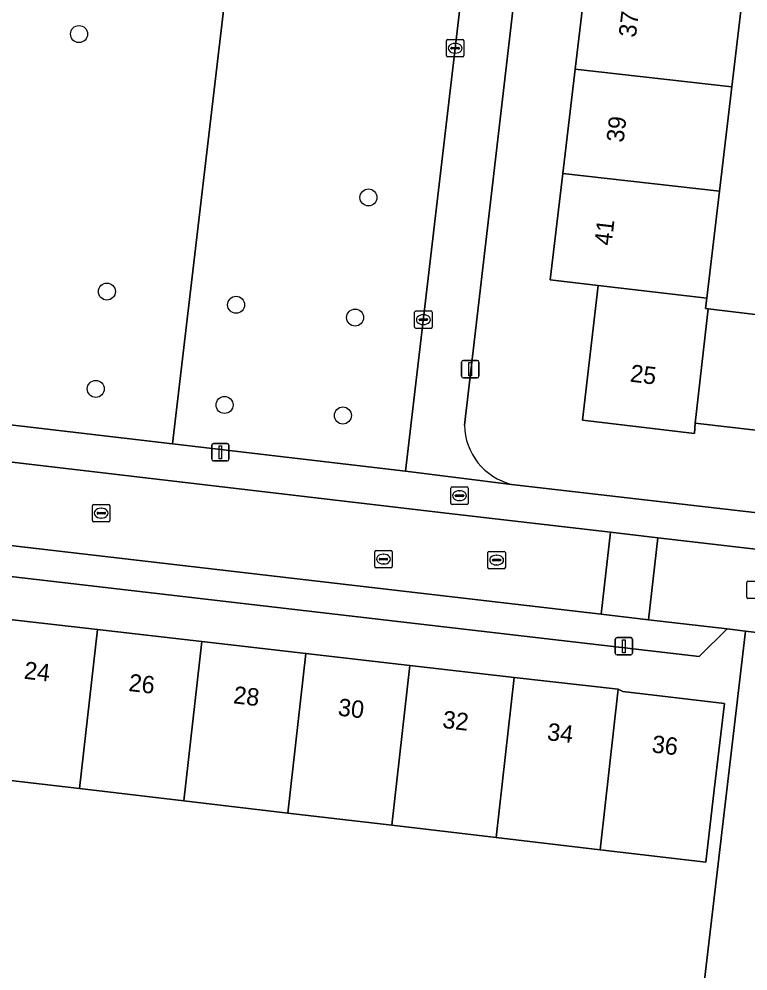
# Model space of a CAD drawing. Extents: x 161241 to 161758, y 384138 to 384885.
# Drawn here: x 161418.6 to 161460.5, y 384397.6 to 384452.3 of the extents above; entities that cross this region are included whole.
import ezdxf

# ---------------------------------------------------------------- set-up
doc = ezdxf.new("R2010")
doc.units = 0
for name, color, linetype in [('IMGEO_Boom', 7, 'Continuous'), ('IMGEO_Brandkraan', 7, 'Continuous'), ('IMGEO_Erf', 7, 'Continuous'), ('IMGEO_Groenvoorziening', 7, 'Continuous'), ('IMGEO_Kolk', 7, 'Continuous'), ('IMGEO_Lichtmast', 7, 'Continuous'), ('IMGEO_Pand', 7, 'Continuous'), ('IMGEO_Pand_nummerreeks', 7, 'Continuous'), ('IMGEO_Parkeervlak_open', 7, 'Continuous'), ('IMGEO_Rijbaan_lokaal_open', 7, 'Continuous'), ('IMGEO_Rioolput', 7, 'Continuous'), ('IMGEO_Voetpad_open', 7, 'Continuous')]:
    doc.layers.add(name, color=color, linetype=linetype)

msp = doc.modelspace()

# ---------------------------------------------------------------- linework, layer by layer
at = {"layer": 'IMGEO_Boom'}
for centre in [(161422.071, 384451.466), (161438.718, 384442.073), (161423.675, 384436.66), (161431.104, 384435.903), (161437.946, 384435.168), (161423.034, 384431.071), (161430.439, 384430.143), (161437.247, 384429.539)]:
    msp.add_circle(centre, 0.489, dxfattribs=at)
at = {"layer": 'IMGEO_Brandkraan'}
for p, q in [((161443.452, 384424.504), (161443.452, 384425.356)), ((161443.527, 384425.43), (161444.379, 384425.43)), ((161444.453, 384425.356), (161444.453, 384424.504)), ((161443.711, 384424.924), (161443.711, 384424.936)), ((161444.149, 384424.887), (161443.751, 384424.887)), ((161443.754, 384424.973), (161444.152, 384424.973)), ((161443.94, 384425.21), (161443.965, 384425.21)), ((161444.195, 384424.936), (161444.195, 384424.924)), ((161444.379, 384424.43), (161443.527, 384424.43)), ((161443.963, 384424.65), (161443.938, 384424.65))]:
    msp.add_line(p, q, dxfattribs=at)
for points in [[(161443.452, 384424.504), (161443.452, 384425.356)], [(161443.527, 384425.43), (161444.379, 384425.43)], [(161444.453, 384425.356), (161444.453, 384424.504)], [(161444.379, 384424.43), (161443.527, 384424.43)]]:
    msp.add_lwpolyline(points, dxfattribs=at)
for centre, radius, start, end in [((161443.529, 384425.354), 0.0765, 91.552, 178.448), ((161443.529, 384425.354), 0.0765, 91.552, 178.448), ((161444.377, 384425.354), 0.0765, 1.552, 88.448), ((161444.377, 384425.354), 0.0765, 1.552, 88.448), ((161443.751, 384424.933), 0.0403, 85.8775, 175.7526), ((161443.748, 384424.923), 0.0366, 178.938, 274.7102), ((161444.152, 384424.93), 0.043, 264.8664, 352.4533), ((161444.156, 384424.935), 0.0386, 1.7309, 96.639), ((161443.529, 384424.506), 0.0765, 181.552, 268.448), ((161443.529, 384424.506), 0.0765, 181.552, 268.448), ((161444.377, 384424.506), 0.0765, 271.552, 358.448), ((161444.377, 384424.506), 0.0765, 271.552, 358.448)]:
    msp.add_arc(centre, radius, start, end, dxfattribs=at)
for centre, major_axis, ratio, start_param, end_param in [((161443.939, 384424.93), (-0.387, 0.002), 0.722429, 4.712389, 7.853982), ((161443.964, 384424.93), (-0.39, 0.002), 0.717154, 1.570796, 4.712389)]:
    msp.add_ellipse(centre, major_axis=major_axis, ratio=ratio, start_param=start_param, end_param=end_param, dxfattribs=at)
at = {"layer": 'IMGEO_Erf'}
for points in [[(161451.223, 384488.839), (161444.232, 384428.985)], [(161505.583, 384423.539), (161496.808, 384424.548), (161496.597, 384422.814), (161488.87, 384423.713), (161484.22, 384424.254), (161484.829, 384429.232), (161481.869, 384429.57), (161479.043, 384429.893), (161478.461, 384424.915), (161473.71, 384425.475), (161466.1, 384426.371), (161466.285, 384428.091), (161457.502, 384429.091), (161457.458, 384428.498), (161451.03, 384429.277), (161451.926, 384437.019), (161449.164, 384437.343), (161449.889, 384443.443), (161450.602, 384449.443), (161451.289, 384455.23)], [(161460.318, 384454.435), (161459.607, 384448.436), (161458.896, 384442.435), (161458.166, 384436.284), (161458.095, 384435.682), (161458.25, 384435.664), (161466.874, 384434.642), (161466.982, 384435.546), (161474.774, 384434.622), (161479.257, 384434.091), (161479.533, 384436.415), (161482.623, 384436.049), (161485.551, 384435.702), (161485.276, 384433.379), (161489.93, 384432.827), (161497.551, 384431.924), (161497.509, 384431.003), (161506.232, 384429.97)], [(161446.947, 384425.581), (161500, 384419.47), (161517.124, 384417.504)], [(161415.847, 384394.67), (161424.15, 384393.701), (161423.913, 384391.799), (161426.306, 384391.565), (161428.717, 384391.33), (161428.41, 384388.19), (161456.596, 384384.852), (161460.391, 384417.148), (161459.347, 384417.271), (161457.727, 384415.687), (161417.974, 384420.297)], [(161417.063, 384417.929), (161423.139, 384417.232), (161429.127, 384416.546), (161435.115, 384415.86), (161441.102, 384415.173), (161447.09, 384414.487), (161453.078, 384413.8), (161453.34, 384413.677), (161459.187, 384412.985), (161458.605, 384408.02), (161458.118, 384403.868), (161452.038, 384404.582), (161446.052, 384405.284), (161440.066, 384405.987), (161434.08, 384406.689), (161428.094, 384407.392), (161422.108, 384408.094), (161415.958, 384408.816)]]:
    msp.add_lwpolyline(points, dxfattribs=at)
msp.add_arc((161447.821, 384429.063), 3.589, 181.2373, 255.9138, dxfattribs=at)
at = {"layer": 'IMGEO_Groenvoorziening'}
msp.add_lwpolyline([(161409.377, 384462.778), (161397.9, 384454.084), (161411.738, 384445.455), (161410.62, 384434.912), (161410.092, 384429.939), (161427.439, 384427.904), (161432.833, 384473.658)], dxfattribs=at)
msp.add_lwpolyline([(161445.975, 384470.082), (161446.228, 384472.086), (161432.833, 384473.658), (161427.439, 384427.904), (161440.852, 384426.331)], close=True, dxfattribs=at)
at = {"layer": 'IMGEO_Kolk'}
for p, q in [((161443.2, 384450.222), (161443.2, 384451.074)), ((161443.275, 384451.148), (161444.127, 384451.148)), ((161444.201, 384451.074), (161444.201, 384450.222)), ((161443.459, 384450.642), (161443.459, 384450.654)), ((161443.897, 384450.605), (161443.499, 384450.605)), ((161443.502, 384450.691), (161443.9, 384450.691)), ((161443.688, 384450.928), (161443.713, 384450.928)), ((161443.943, 384450.654), (161443.943, 384450.642)), ((161444.127, 384450.148), (161443.275, 384450.148)), ((161443.711, 384450.368), (161443.686, 384450.368)), ((161441.373, 384434.622), (161441.373, 384435.474)), ((161441.448, 384435.548), (161442.3, 384435.548)), ((161441.861, 384435.328), (161441.886, 384435.328)), ((161442.374, 384435.474), (161442.374, 384434.622)), ((161441.632, 384435.042), (161441.632, 384435.054)), ((161442.07, 384435.005), (161441.672, 384435.005)), ((161441.675, 384435.091), (161442.073, 384435.091)), ((161441.884, 384434.768), (161441.859, 384434.768)), ((161442.116, 384435.054), (161442.116, 384435.042)), ((161442.3, 384434.548), (161441.448, 384434.548)), ((161422.848, 384423.5), (161422.848, 384424.352)), ((161422.923, 384424.426), (161423.775, 384424.426)), ((161423.336, 384424.206), (161423.361, 384424.206)), ((161423.849, 384424.352), (161423.849, 384423.5)), ((161423.107, 384423.92), (161423.107, 384423.932)), ((161423.545, 384423.883), (161423.147, 384423.883)), ((161423.15, 384423.969), (161423.548, 384423.969)), ((161423.359, 384423.646), (161423.334, 384423.646)), ((161423.591, 384423.932), (161423.591, 384423.92)), ((161423.775, 384423.426), (161422.923, 384423.426)), ((161445.587, 384420.803), (161445.587, 384421.655)), ((161445.662, 384421.729), (161446.514, 384421.729)), ((161446.075, 384421.509), (161446.1, 384421.509)), ((161446.588, 384421.655), (161446.588, 384420.803)), ((161445.846, 384421.223), (161445.846, 384421.235)), ((161446.284, 384421.186), (161445.886, 384421.186)), ((161445.889, 384421.272), (161446.287, 384421.272)), ((161446.098, 384420.949), (161446.073, 384420.949)), ((161446.33, 384421.235), (161446.33, 384421.223)), ((161446.514, 384420.729), (161445.662, 384420.729)), ((161460.466, 384419.094), (161460.466, 384419.946)), ((161460.541, 384420.02), (161461.393, 384420.02)), ((161461.393, 384419.02), (161460.541, 384419.02))]:
    msp.add_line(p, q, dxfattribs=at)
for points in [[(161443.2, 384450.222), (161443.2, 384451.074)], [(161443.275, 384451.148), (161444.127, 384451.148)], [(161444.201, 384451.074), (161444.201, 384450.222)], [(161444.127, 384450.148), (161443.275, 384450.148)], [(161441.373, 384434.622), (161441.373, 384435.474)], [(161441.448, 384435.548), (161442.3, 384435.548)], [(161442.374, 384435.474), (161442.374, 384434.622)], [(161442.3, 384434.548), (161441.448, 384434.548)], [(161422.848, 384423.5), (161422.848, 384424.352)], [(161422.923, 384424.426), (161423.775, 384424.426)], [(161423.849, 384424.352), (161423.849, 384423.5)], [(161423.775, 384423.426), (161422.923, 384423.426)], [(161445.587, 384420.803), (161445.587, 384421.655)], [(161445.662, 384421.729), (161446.514, 384421.729)], [(161446.588, 384421.655), (161446.588, 384420.803)], [(161446.514, 384420.729), (161445.662, 384420.729)], [(161460.466, 384419.094), (161460.466, 384419.946)], [(161460.541, 384420.02), (161461.393, 384420.02)], [(161461.393, 384419.02), (161460.541, 384419.02)]]:
    msp.add_lwpolyline(points, dxfattribs=at)
for centre, radius, start, end in [((161443.277, 384451.072), 0.0765, 91.552, 178.448), ((161443.277, 384451.072), 0.0765, 91.552, 178.448), ((161444.125, 384451.072), 0.0765, 1.552, 88.448), ((161444.125, 384451.072), 0.0765, 1.552, 88.448), ((161443.499, 384450.651), 0.0403, 85.8775, 175.7526), ((161443.496, 384450.641), 0.0366, 178.938, 274.7102), ((161443.9, 384450.648), 0.043, 264.8664, 352.4533), ((161443.904, 384450.653), 0.0386, 1.7309, 96.639), ((161443.277, 384450.224), 0.0765, 181.552, 268.448), ((161443.277, 384450.224), 0.0765, 181.552, 268.448), ((161444.125, 384450.224), 0.0765, 271.552, 358.448), ((161444.125, 384450.224), 0.0765, 271.552, 358.448), ((161441.45, 384435.472), 0.0765, 91.552, 178.448), ((161441.45, 384435.472), 0.0765, 91.552, 178.448), ((161442.298, 384435.472), 0.0765, 1.552, 88.448), ((161442.298, 384435.472), 0.0765, 1.552, 88.448), ((161441.45, 384434.624), 0.0765, 181.552, 268.448), ((161441.45, 384434.624), 0.0765, 181.552, 268.448), ((161441.672, 384435.051), 0.0403, 85.8775, 175.7526), ((161441.669, 384435.041), 0.0366, 178.938, 274.7102), ((161442.073, 384435.048), 0.043, 264.8664, 352.4533), ((161442.077, 384435.053), 0.0386, 1.7309, 96.639), ((161442.298, 384434.624), 0.0765, 271.552, 358.448), ((161442.298, 384434.624), 0.0765, 271.552, 358.448), ((161422.925, 384424.35), 0.0765, 91.552, 178.448), ((161422.925, 384424.35), 0.0765, 91.552, 178.448), ((161423.773, 384424.35), 0.0765, 1.552, 88.448), ((161423.773, 384424.35), 0.0765, 1.552, 88.448), ((161423.147, 384423.929), 0.0403, 85.8775, 175.7526), ((161423.144, 384423.919), 0.0366, 178.938, 274.7102), ((161423.548, 384423.926), 0.043, 264.8664, 352.4533), ((161423.552, 384423.931), 0.0386, 1.7309, 96.639), ((161422.925, 384423.502), 0.0765, 181.552, 268.448), ((161422.925, 384423.502), 0.0765, 181.552, 268.448), ((161423.773, 384423.502), 0.0765, 271.552, 358.448), ((161423.773, 384423.502), 0.0765, 271.552, 358.448), ((161445.664, 384421.653), 0.0765, 91.552, 178.448), ((161445.664, 384421.653), 0.0765, 91.552, 178.448), ((161446.512, 384421.653), 0.0765, 1.552, 88.448), ((161446.512, 384421.653), 0.0765, 1.552, 88.448), ((161445.886, 384421.232), 0.0403, 85.8775, 175.7526), ((161445.883, 384421.222), 0.0366, 178.938, 274.7102), ((161446.287, 384421.229), 0.043, 264.8664, 352.4533), ((161446.291, 384421.234), 0.0386, 1.7309, 96.639), ((161445.664, 384420.805), 0.0765, 181.552, 268.448), ((161445.664, 384420.805), 0.0765, 181.552, 268.448), ((161446.512, 384420.805), 0.0765, 271.552, 358.448), ((161446.512, 384420.805), 0.0765, 271.552, 358.448), ((161460.543, 384419.944), 0.0765, 91.552, 178.448), ((161460.543, 384419.944), 0.0765, 91.552, 178.448), ((161460.543, 384419.096), 0.0765, 181.552, 268.448), ((161460.543, 384419.096), 0.0765, 181.552, 268.448)]:
    msp.add_arc(centre, radius, start, end, dxfattribs=at)
for centre, major_axis, ratio, start_param, end_param in [((161443.687, 384450.648), (-0.387, 0.002), 0.722429, 4.712389, 7.853982), ((161443.712, 384450.648), (-0.39, 0.002), 0.717154, 1.570796, 4.712389), ((161441.86, 384435.048), (-0.387, 0.002), 0.722429, 4.712389, 7.853982), ((161441.885, 384435.048), (-0.39, 0.002), 0.717154, 1.570796, 4.712389), ((161423.335, 384423.926), (-0.387, 0.002), 0.722429, 4.712389, 7.853982), ((161423.36, 384423.926), (-0.39, 0.002), 0.717154, 1.570796, 4.712389), ((161446.074, 384421.229), (-0.387, 0.002), 0.722429, 4.712389, 7.853982), ((161446.099, 384421.229), (-0.39, 0.002), 0.717154, 1.570796, 4.712389)]:
    msp.add_ellipse(centre, major_axis=major_axis, ratio=ratio, start_param=start_param, end_param=end_param, dxfattribs=at)
at = {"layer": 'IMGEO_Lichtmast'}
for p, q in [((161444.075, 384431.801), (161444.075, 384432.601)), ((161444.075, 384432.601), (161444.075, 384431.801)), ((161444.175, 384432.701), (161444.965, 384432.701)), ((161444.965, 384432.701), (161444.175, 384432.701)), ((161445.065, 384432.601), (161445.065, 384431.801)), ((161445.065, 384431.801), (161445.065, 384432.601)), ((161444.965, 384431.701), (161444.175, 384431.701)), ((161444.175, 384431.701), (161444.965, 384431.701)), ((161429.704, 384427.026), (161429.704, 384427.826)), ((161429.704, 384427.826), (161429.704, 384427.026)), ((161429.804, 384427.926), (161430.594, 384427.926)), ((161430.594, 384427.926), (161429.804, 384427.926)), ((161430.694, 384427.826), (161430.694, 384427.026)), ((161430.694, 384427.026), (161430.694, 384427.826)), ((161430.594, 384426.926), (161429.804, 384426.926)), ((161429.804, 384426.926), (161430.594, 384426.926)), ((161452.91, 384415.874), (161452.91, 384416.674)), ((161452.91, 384416.674), (161452.91, 384415.874)), ((161453.01, 384416.774), (161453.8, 384416.774)), ((161453.8, 384416.774), (161453.01, 384416.774)), ((161453.9, 384416.674), (161453.9, 384415.874)), ((161453.9, 384415.874), (161453.9, 384416.674)), ((161453.8, 384415.774), (161453.01, 384415.774)), ((161453.01, 384415.774), (161453.8, 384415.774))]:
    msp.add_line(p, q, dxfattribs=at)
for points in [[(161444.495, 384432.576), (161444.645, 384432.576), (161444.645, 384431.826), (161444.495, 384431.826), (161444.495, 384432.576)], [(161430.124, 384427.801), (161430.274, 384427.801), (161430.274, 384427.051), (161430.124, 384427.051), (161430.124, 384427.801)], [(161453.33, 384416.649), (161453.48, 384416.649), (161453.48, 384415.899), (161453.33, 384415.899), (161453.33, 384416.649)]]:
    msp.add_lwpolyline(points, dxfattribs=at)
for centre, start, end in [((161444.175, 384432.601), 90, 180), ((161444.175, 384432.601), 90, 180), ((161444.965, 384432.601), 0, 90), ((161444.965, 384432.601), 360, 90), ((161444.175, 384431.801), 180, 270), ((161444.175, 384431.801), 180, 270), ((161444.965, 384431.801), 270, 0), ((161444.965, 384431.801), 270, 0), ((161429.804, 384427.826), 90, 180), ((161429.804, 384427.826), 90, 180), ((161430.594, 384427.826), 0, 90), ((161430.594, 384427.826), 360, 90), ((161429.804, 384427.026), 180, 270), ((161429.804, 384427.026), 180, 270), ((161430.594, 384427.026), 270, 0), ((161430.594, 384427.026), 270, 0), ((161453.01, 384416.674), 90, 180), ((161453.01, 384416.674), 90, 180), ((161453.8, 384416.674), 0, 90), ((161453.8, 384416.674), 360, 90), ((161453.01, 384415.874), 180, 270), ((161453.01, 384415.874), 180, 270), ((161453.8, 384415.874), 270, 0), ((161453.8, 384415.874), 270, 0)]:
    msp.add_arc(centre, 0.1, start, end, dxfattribs=at)
at = {"layer": 'IMGEO_Pand'}
for points in [[(161451.061, 384455.472), (161451.038, 384455.281), (161451.289, 384455.23), (161450.602, 384449.443), (161459.607, 384448.436), (161460.318, 384454.435)], [(161458.896, 384442.435), (161459.607, 384448.436), (161450.602, 384449.443), (161449.889, 384443.443)], [(161449.889, 384443.443), (161449.164, 384437.343), (161451.926, 384437.019), (161458.166, 384436.284), (161458.896, 384442.435)], [(161458.25, 384435.664), (161458.095, 384435.682), (161458.166, 384436.284), (161451.926, 384437.019), (161451.03, 384429.277), (161457.458, 384428.498), (161457.502, 384429.091)], [(161458.25, 384435.664), (161457.502, 384429.091), (161466.285, 384428.091), (161466.874, 384434.642)], [(161416.056, 384409.721), (161415.958, 384408.816), (161422.108, 384408.094), (161423.139, 384417.232), (161417.063, 384417.929), (161416.852, 384416.18)], [(161429.127, 384416.546), (161423.139, 384417.232), (161422.108, 384408.094), (161428.094, 384407.392)], [(161428.094, 384407.392), (161434.08, 384406.689), (161435.115, 384415.86), (161429.127, 384416.546)], [(161434.08, 384406.689), (161440.066, 384405.987), (161441.102, 384415.173), (161435.115, 384415.86)], [(161447.09, 384414.487), (161441.102, 384415.173), (161440.066, 384405.987), (161446.052, 384405.284)], [(161446.052, 384405.284), (161452.038, 384404.582), (161453.078, 384413.8), (161447.09, 384414.487)], [(161452.038, 384404.582), (161458.118, 384403.868), (161458.605, 384408.02), (161459.187, 384412.985), (161453.34, 384413.677), (161453.078, 384413.8)]]:
    msp.add_lwpolyline(points, close=True, dxfattribs=at)
at = {"layer": 'IMGEO_Parkeervlak_open'}
msp.add_lwpolyline([(161417.282, 384422.167), (161417.974, 384420.297), (161457.727, 384415.687), (161459.347, 384417.271), (161454.814, 384417.799), (161452.092, 384418.115)], close=True, dxfattribs=at)
at = {"layer": 'IMGEO_Rijbaan_lokaal_open'}
for points in [[(161417.282, 384422.167), (161452.092, 384418.115), (161452.639, 384422.825), (161443.686, 384423.864), (161404.653, 384428.447), (161404.094, 384423.73)], [(161454.814, 384417.799), (161455.361, 384422.51), (161452.639, 384422.825), (161452.092, 384418.115)]]:
    msp.add_lwpolyline(points, close=True, dxfattribs=at)
for points in [[(161516.896, 384415.376), (161500, 384417.331), (161455.361, 384422.51), (161454.814, 384417.799), (161459.347, 384417.271), (161460.391, 384417.148), (161464.436, 384416.673), (161465.637, 384416.532), (161489.559, 384413.756), (161500, 384412.531), (161510.318, 384411.321), (161514.204, 384410.875), (161523.243, 384409.923)], [(161506.638, 384379.095), (161463.961, 384384), (161461.689, 384384.202), (161461.694, 384384.264), (161460.643, 384384.386), (161464.436, 384416.673), (161460.391, 384417.148), (161456.596, 384384.852), (161428.41, 384388.19), (161425.953, 384388.43), (161423.606, 384388.659), (161423.913, 384391.799), (161424.15, 384393.701), (161415.847, 384394.67)]]:
    msp.add_lwpolyline(points, dxfattribs=at)
at = {"layer": 'IMGEO_Rioolput'}
for p, q in [((161439.077, 384420.858), (161439.077, 384421.71)), ((161439.152, 384421.784), (161440.004, 384421.784)), ((161439.565, 384421.564), (161439.59, 384421.564)), ((161440.078, 384421.71), (161440.078, 384420.858)), ((161439.336, 384421.278), (161439.336, 384421.29)), ((161439.774, 384421.241), (161439.376, 384421.241)), ((161439.379, 384421.327), (161439.777, 384421.327)), ((161439.588, 384421.004), (161439.563, 384421.004)), ((161439.82, 384421.29), (161439.82, 384421.278)), ((161440.004, 384420.784), (161439.152, 384420.784))]:
    msp.add_line(p, q, dxfattribs=at)
for points in [[(161439.077, 384420.858), (161439.077, 384421.71)], [(161439.152, 384421.784), (161440.004, 384421.784)], [(161440.078, 384421.71), (161440.078, 384420.858)], [(161440.004, 384420.784), (161439.152, 384420.784)]]:
    msp.add_lwpolyline(points, dxfattribs=at)
for centre, radius, start, end in [((161439.154, 384421.708), 0.0765, 91.552, 178.448), ((161439.154, 384421.708), 0.0765, 91.552, 178.448), ((161440.002, 384421.708), 0.0765, 1.552, 88.448), ((161440.002, 384421.708), 0.0765, 1.552, 88.448), ((161439.376, 384421.287), 0.0403, 85.8775, 175.7526), ((161439.373, 384421.277), 0.0366, 178.938, 274.7102), ((161439.777, 384421.284), 0.043, 264.8664, 352.4533), ((161439.781, 384421.289), 0.0386, 1.7309, 96.639), ((161439.154, 384420.86), 0.0765, 181.552, 268.448), ((161439.154, 384420.86), 0.0765, 181.552, 268.448), ((161440.002, 384420.86), 0.0765, 271.552, 358.448), ((161440.002, 384420.86), 0.0765, 271.552, 358.448)]:
    msp.add_arc(centre, radius, start, end, dxfattribs=at)
for centre, major_axis, ratio, start_param, end_param in [((161439.564, 384421.284), (-0.387, 0.002), 0.722429, 4.712389, 7.853982), ((161439.589, 384421.284), (-0.39, 0.002), 0.717154, 1.570796, 4.712389)]:
    msp.add_ellipse(centre, major_axis=major_axis, ratio=ratio, start_param=start_param, end_param=end_param, dxfattribs=at)
at = {"layer": 'IMGEO_Voetpad_open'}
for points in [[(161454.323, 384491.094), (161448.511, 384491.779), (161447.091, 384479.626), (161446.649, 384475.767), (161446.41, 384473.599), (161446.228, 384472.086), (161445.975, 384470.082), (161440.852, 384426.331), (161446.947, 384425.581)], [(161444.232, 384428.985), (161451.223, 384488.839)]]:
    msp.add_lwpolyline(points, dxfattribs=at)
msp.add_lwpolyline([(161427.439, 384427.904), (161410.092, 384429.939), (161407.225, 384430.276), (161404.443, 384430.602), (161399.514, 384431.19), (161393.511, 384431.885), (161387.488, 384432.576), (161336.535, 384438.485), (161336.257, 384436.376), (161382.402, 384431.06), (161401.922, 384428.768), (161404.653, 384428.447), (161443.686, 384423.864), (161452.639, 384422.825), (161455.361, 384422.51), (161500, 384417.331), (161516.896, 384415.376), (161517.124, 384417.504), (161500, 384419.47), (161446.947, 384425.581), (161440.852, 384426.331)], close=True, dxfattribs=at)
msp.add_arc((161447.821, 384429.063), 3.589, 181.2373, 255.9138, dxfattribs=at)

# ---------------------------------------------------------------- texts
at = {"layer": 'IMGEO_Pand_nummerreeks'}
for s, rotation, p in [('37', 83.3342, (161454.091, 384451.238)), ('39', 83.3342, (161453.385, 384445.199)), ('41', 83.3342, (161452.692, 384439.273)), ('25', 353.0901, (161453.727, 384431.489)), ('24', 353.3059, (161418.869, 384414.415)), ('26', 353.3059, (161424.887, 384413.708)), ('28', 353.3059, (161430.907, 384413.001)), ('30', 353.3059, (161436.925, 384412.295)), ('32', 353.3059, (161442.937, 384411.589)), ('34', 353.3059, (161448.957, 384410.883)), ('36', 353.3059, (161454.975, 384410.177))]:
    msp.add_text(s, height=1, rotation=rotation, dxfattribs=at).set_placement(p)

doc.saveas('drawing.dxf')
